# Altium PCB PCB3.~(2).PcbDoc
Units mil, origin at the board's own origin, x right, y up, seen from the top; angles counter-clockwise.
Board outline 6000 x 4000 mil, 2 copper layers (Top Layer, Bottom Layer); 11 components, 12 nets, 36 pads, 0 vias.
Unrouted connection lines stored in the file: 21.
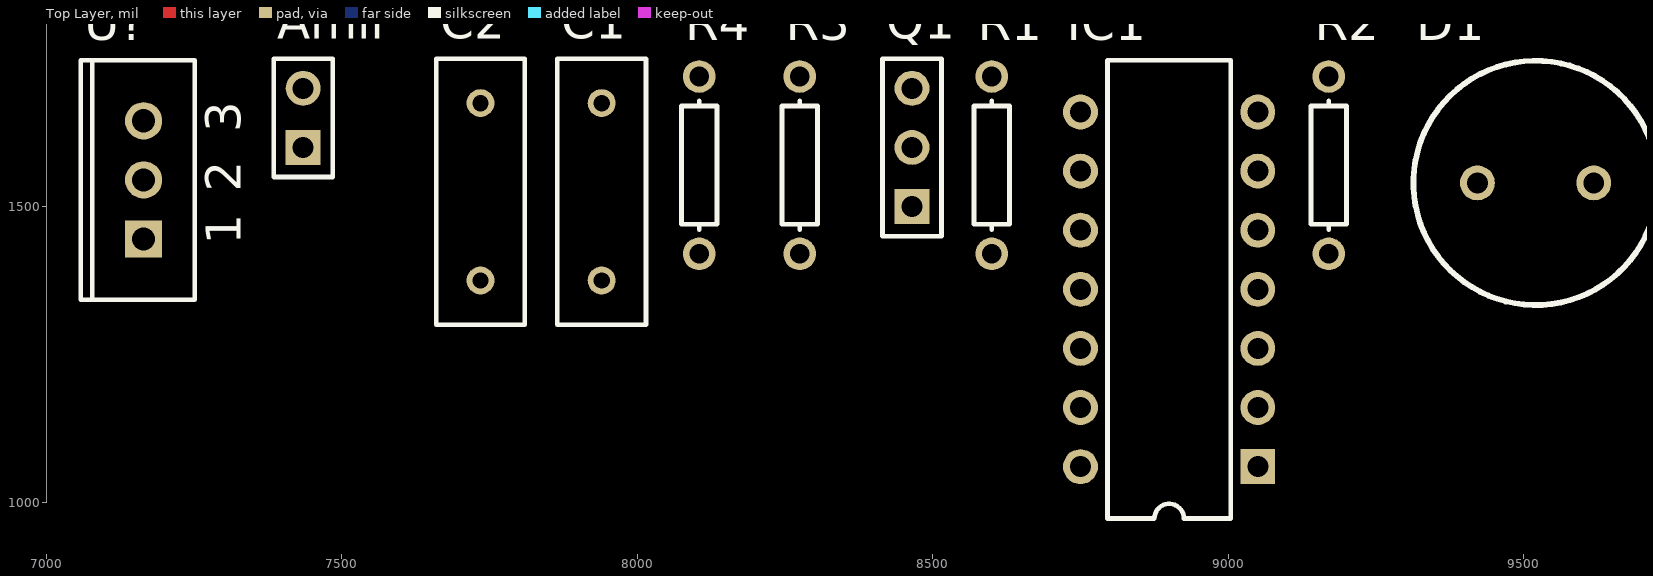
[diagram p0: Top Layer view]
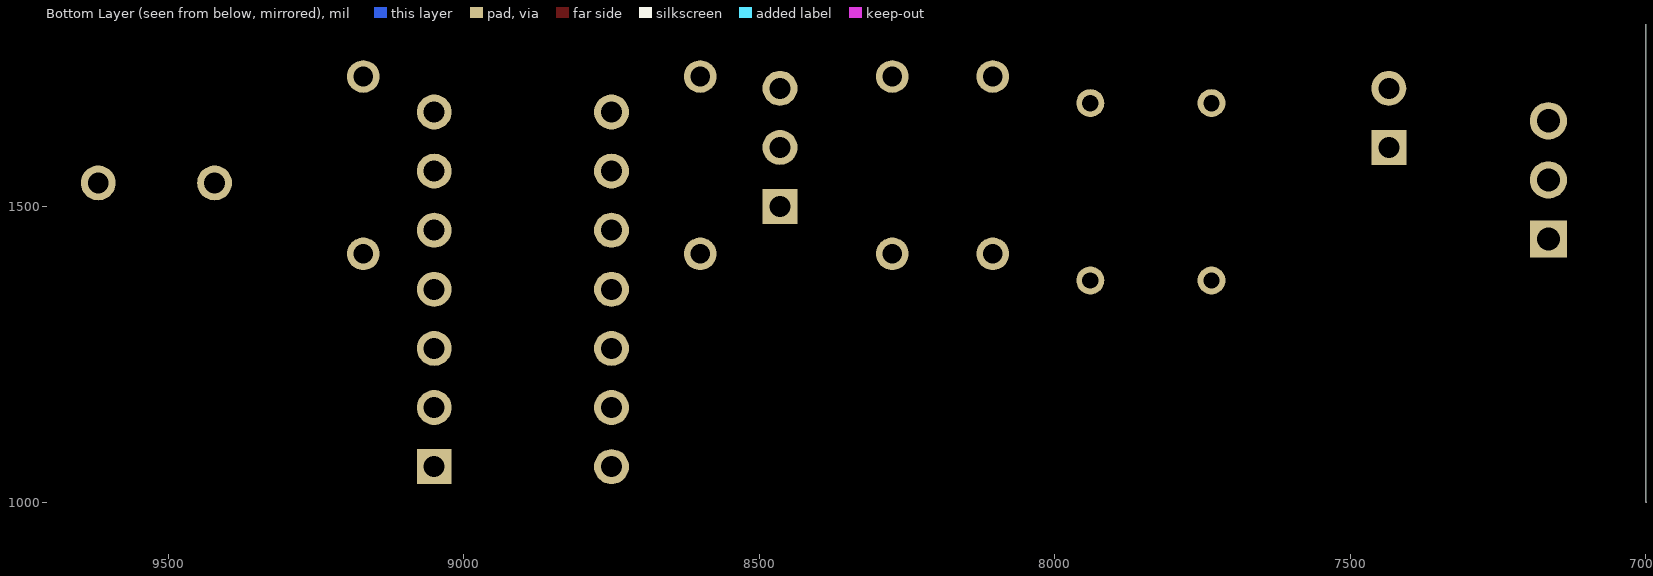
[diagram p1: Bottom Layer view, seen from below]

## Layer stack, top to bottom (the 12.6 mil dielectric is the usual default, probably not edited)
Top Layer: signal copper 1.4
Dielectric: dielectric 12.6, FR-4, Dk 4.8
Bottom Layer: signal copper 1.4

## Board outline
1000,1000 7000,1000 7000,5000 1000,5000

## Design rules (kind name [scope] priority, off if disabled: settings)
Clearance [All] p1: gap=10
PolygonConnect [All] p1: connectstyle=Relief reliefconductorwidth=10 reliefentries=4 polygonreliefangle="90 Angle"
RoomDefinition Sheet1 [InComponentClass('Sheet1')] p1: confinementstyle=ConfineIn formatcopy=TRUE lockcomponents=FALSE outline 7045,960 9740,960 9740,1860 7045,1860
RoutingVias [All] p1: holewidth=28 width=50 viastyle="Through Hole" minholewidth=28 minwidth=50 maxholewidth=28 maxwidth=50
SilkscreenOverComponentPads [All] p1: minsilkscreentomaskgap=10
SolderMaskExpansion [All] p1: expansion=4
Width [All] p1: maxlimit=10 minlimit=10 preferedwidth=10
27 further rules are at their usual default settings.

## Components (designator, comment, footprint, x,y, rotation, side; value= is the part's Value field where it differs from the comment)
Amir "Header 2" HDR1X2 7435,1600 r90 top
C1 "Cap" RAD-0.3 7940,1525 r90 top
C2 "Cap" RAD-0.3 7735,1525 r90 top
D1 "LED0" RB5-10.5 9520,1540 r0 top
IC1 "MC74HC00AN" 646-06 8900,1360 r90 top
Q1 "NPN" HDR1X3 8465,1500 r90 top
R1 "Res1" AXIAL-0.3 8600,1570 r90 top
R2 "Res1" AXIAL-0.3 9170,1570 r90 top
R3 "Res1" AXIAL-0.3 8275,1570 r90 top
R4 "Res1" AXIAL-0.3 8105,1570 r90 top
U? "MC7805ACT" 221A-04 7165,1545 r90 top

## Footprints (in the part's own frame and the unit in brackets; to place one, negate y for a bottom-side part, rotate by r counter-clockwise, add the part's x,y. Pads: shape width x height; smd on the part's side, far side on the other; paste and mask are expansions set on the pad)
221A-04 [mm] "TO, Thru-Hole, Vertical, Heatsink Mounted; 3 In-Line Leads; Pitch 2.54 mm"
  rect 1.6x1.6 hole 1: 1(-2.54,0)
  round 1.6 hole 1: 2(0,0) 3(2.54,0)
  silkscreen extent -5.15,-2.2 5.15,2.7
646-06 [mm] "DIP; 14 Leads; Row Spacing 7.62 mm; Pitch 2.54 mm"
  rect 1.5x1.5 hole 0.9: 1(-7.62,-3.81)
  round 1.5 hole 0.9: 2(-5.08,-3.81) 3(-2.54,-3.81) 4(0,-3.81) 5(2.54,-3.81) 6(5.08,-3.81) 7(7.62,-3.81) 8(7.62,3.81) 9(5.08,3.81) 10(2.54,3.81) 11(0,3.81) 12(-2.54,3.81) 13(-5.08,3.81) 14(-7.62,3.81)
  silkscreen extent -9.85,-2.65 9.85,2.65
AXIAL-0.3 [mm] "Axial Device, Thru-Hole; 2 Leads; 0.3 in Pin Spacing"
  round 1.4 hole 0.85: 1(-3.81,0) 2(3.81,0)
  silkscreen extent -2.77,-0.76 2.77,0.76
HDR1X2 [mm] "Connector; Header; 2 Position"
  rect 1.5x1.5 hole 0.9: 1(0,0)
  round 1.5 hole 0.9: 2(2.54,0)
  silkscreen extent -1.27,-1.27 3.81,1.27
HDR1X3 [mm] "Connector; Header; 3 Position"
  rect 1.5x1.5 hole 0.9: 1(0,0)
  round 1.5 hole 0.9: 2(2.54,0) 3(5.08,0)
  silkscreen extent -1.27,-1.27 6.35,1.27
RAD-0.3 [mm] "Radial Cap, Thru-Hole; 2 Leads; 0.3 in Pin Spacing"
  round 1.2 hole 0.7: 1(-3.81,0) 2(3.81,0)
  silkscreen extent -5.71,-1.91 5.71,1.91
RB5-10.5 [mm] "Motor, General Kind; 2 Leads"
  round 1.5 hole 0.9: 1(-2.5,0) 2(2.5,0)
  silkscreen extent -5.25,-5.25 5.25,5.25

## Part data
Amir: "Header, 2-Pin"
C1 C2: "Capacitor"
D1: "Typical INFRARED GaAs LED"
IC1: "Quad 2-Input NAND Gate"
Q1: "NPN Bipolar Transistor"
R1 R2 R3 R4: "Resistor"
U?: "3-Terminal Positive Fixed Voltage Regulator"

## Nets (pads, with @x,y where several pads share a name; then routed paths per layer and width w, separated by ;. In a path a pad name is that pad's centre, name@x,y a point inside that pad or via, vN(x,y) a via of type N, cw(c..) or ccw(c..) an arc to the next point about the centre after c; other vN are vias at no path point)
GND: Amir.2 C2.1 IC1.7 Q1.3 U?.2
NET1: IC1.8 R1.1 R4.2
NetAmir_1: Amir.1 U?.1
NetC1_1: C1.1 R3.1 R4.1
NetC1_2: C1.2 IC1.6 IC1.9 IC1.10
NetD1_2: D1.2 R2.2
NetIC1_2: IC1.2 R3.2
NetIC1_3: IC1.3 IC1.5
NetQ1_1: Q1.1 R2.1
NetQ1_2: Q1.2 R1.2
PHL: C2.2 D1.1 IC1.1 IC1.4 U?.3
VDD: IC1.14
pads on no net: IC1.11 IC1.12 IC1.13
